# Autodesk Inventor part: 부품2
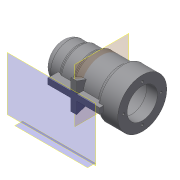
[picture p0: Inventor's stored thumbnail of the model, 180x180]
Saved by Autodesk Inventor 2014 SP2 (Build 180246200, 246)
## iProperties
Created: 2016-06
Part Number: 부품2
Material: 일반
Document SubType Name: Modeling
Designer: 201-20
Density: 1 g/cm^3
Appearance: 기본값
Author: 201-20
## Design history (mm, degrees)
sketch "스케치1"
  geometry: L1 (-56, 0)-(56, 0); L2 (56, 0)-(56, 34); L3 (56, 34)-(28, 34); L4 (28, 34)-(28, 30); L5 (28, 30)-(-11, 30); L6 (-11, 30)-(-11, 27); L7 (-11, 27)-(-31, 27); L8 (-31, 27)-(-31, 25); L9 (-31, 25)-(-56, 25); L10 (-56, 25)-(-56, 0); L11 (56, 0)-(56, 21); L12 (41, 21)-(56, 21); L13 (41, 21)-(41, 24); L14 (41, 24)-(-13, 24); L15 (-13, 24)-(-13, 21); L16 (-13, 21)-(-25, 21); L17 (-25, 21)-(-25, 17.5); L18 (-25, 17.5)-(-43, 17.5); L19 (-43, 17.5)-(-43, 16); L20 (-43, 16)-(-47, 16); L21 (-47, 16)-(-47, 10.5); L22 (-47, 10.5)-(-50, 10.5); L23 (-50, 10.5)-(-50, 0); 2 further points
  constraints: 46 end point, 12 parallel, 9 perpendicular, 2 point on line, 1 coincident, 1 horizontal, 1 midpoint
  dimensions: "d0" = 112 distance of L1.start L1.end; "d1" = 68 diameter of L3 L1; "d2" = 60 diameter of L5 L1; "d3" = 54 diameter of L7 L1; "d4" = 50 diameter of L9 L1; "d5" = 25 distance of L8.end L9.end; "d6" = 45 distance from line of L6.end L10; "d7" = 84 distance from line of L4.end L10; "d8" = 42 diameter of L12 L1; "d9" = 48 diameter of L14 L1; "d10" = 42 diameter of L16 L1; "d11" = 35 diameter of L18 L1; "d12" = 32 diameter of L20 L1; "d13" = 21 diameter of L22 L1; "d14" = 3 distance of L21.end L22.end; "d15" = 15 distance of L12.start L11.end; "d16" = 54 distance of L13.end L14.end; "d17" = 12 distance of L15.end L16.end; "d18" = 18 distance of L17.end L18.end; "d19" = 4 distance of L19.end L20.end; "d20" = 112 distance from line of L2.end L10
revolve "회전1" sketch "스케치1" stored, may be unused: angle "d21" = 90 deg
fillet "모깎기1" dims "d22" = 10
fillet "모깎기2" dims "d23" = 3
sketch "스케치2" dims "d24" = 52
  geometry: 3 further points
  constraints: 1 coincident, 1 vertical alignment, 2 other
hole "구멍1" sketch "스케치2" at (0, 26) diameter "d25" = 3.242; stored, may be unused: countersink angle "d29" = 90 deg, drill point angle "d31" = 118 deg; dims "d26" = 8, "d27" = 4, "d28" = 2, "d30" = 11
node "작업 평면1"
sketch "스케치3"
  geometry: L1 (-56, 34)-(-56, -34) reference; L2 (-56, 35)-(56, 35); L3 (56, 35)-(56, -35); L4 (56, -35)-(-56, -35); L5 (-56, -35)-(-56, 35); 2 further points
  constraints: 8 end point, 2 parallel, 1 horizontal, 1 horizontal alignment, 1 midpoint, 1 perpendicular
  dimensions: "d36" = 112 distance of L3.end L4.end; "d37" = 70 distance of L2.end L3.end
extrude "돌출1" join sketch "스케치3" distance "d38" = 10; taper "d39" = 0 deg
sketch "스케치4"
  geometry: L1 (46, -25)-(-46, -25); L2 (-46, -25)-(-46, 25); L3 (-46, 25)-(46, 25); L4 (46, 25)-(46, -25); 3 further points
  constraints: 8 end point, 2 midpoint, 2 parallel, 1 horizontal, 1 horizontal alignment, 1 perpendicular, 1 vertical alignment
  dimensions: "d40" = 92 distance of L2.end L3.end; "d41" = 50 distance of L1.end L2.end
hole "구멍2" sketch "스케치4" at (-46, -25), (46, -25), (-46, 25), (46, 25) diameter "d42" = 5; stored, may be unused: countersink angle "d46" = 90 deg, drill point angle "d48" = 118 deg; dims "d43" = 8, "d44" = 9, "d45" = 4, "d47" = 11
fillet "모깎기3" dims "d49" = 10
sketch "스케치5"
  geometry: L1 (-36, 4)-(36, 4); L2 (36, 4)-(36, -4); L3 (36, -4)-(-36, -4); L4 (-36, -4)-(-36, 4); L5 (-56, -25)-(-56, 25) reference; L6 (56, 25)-(56, -25) reference; 1 further point
  constraints: 8 end point, 2 parallel, 1 horizontal, 1 perpendicular
  dimensions: "d50" = 20 distance between parallel lines of L5 L4; "d51" = 20 distance between parallel lines of L6 L2; "d52" = 8 distance between parallel lines of L3 L1; "d53" = 4 vertical distance of L1.start point (0, 0)
extrude "돌출2" join sketch "스케치5" stored distance "d54" = 10; taper "d55" = 0 deg
node "작업 평면2"
sketch "스케치6"
  geometry: L1 (-25, -60)-(25, -60) reference; L2 (-4, -60)-(-4, -33.764) reference; L3 (-35, -60)-(-35, -70) reference; L4 (-28, -60)-(-15.509, -25.68); L5 (-35, -60)-(-25, -60) reference; A1 r 30 centre (0, 0) between (4, -29.732) and (-4, -29.732) reference; 1 further point
  constraints: 2 end point, 1 point on circle, 1 point on line
  dimensions: "d57" = 110 deg angle of L5 L4; "d58" = 7 distance from line of L4.start L3
feature "리브1" sketch "스케치6" dims "d59" = 1, "d60" = 8, "d61" = 0, "d62" = 0, "d63" = 1, "d64" = 1
node "작업 평면3"
sketch "스케치7"
  geometry: L1 (-22, 31)-(121, 31); L2 (121, 31)-(121, -10); L3 (121, -10)-(-22, -10); L4 (-22, -10)-(-22, 31); 1 further point
  constraints: 8 end point, 2 parallel, 1 horizontal, 1 perpendicular
extrude "돌출3" cut sketch "스케치7" distance "d66" = 100; taper "d67" = 0 deg
node "솔리드1"
pattern_circular "원형 패턴1" dims angle "d33" = 360 deg
mirror "대칭1"
other parameters: "d56" = -56
